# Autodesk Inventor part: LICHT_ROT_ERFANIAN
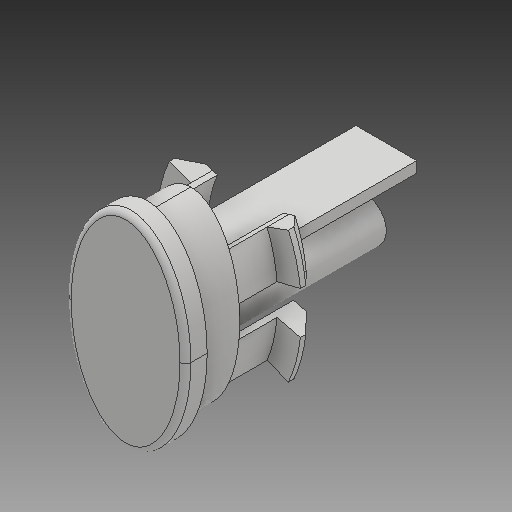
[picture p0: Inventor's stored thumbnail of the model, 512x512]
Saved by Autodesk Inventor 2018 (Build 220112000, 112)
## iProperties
Created: 2019-01
Part Number: LICHT_ROT_ERFANIAN
Material: Generisch
Document SubType Name: Modeling
Designer: zand
Density: 1 g/cm^3
Appearance: Vorgabe
Author: zand
Revision Number: 14LAST_VERSION
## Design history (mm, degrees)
feature "Basis1"
node "Volumenkörper1"
